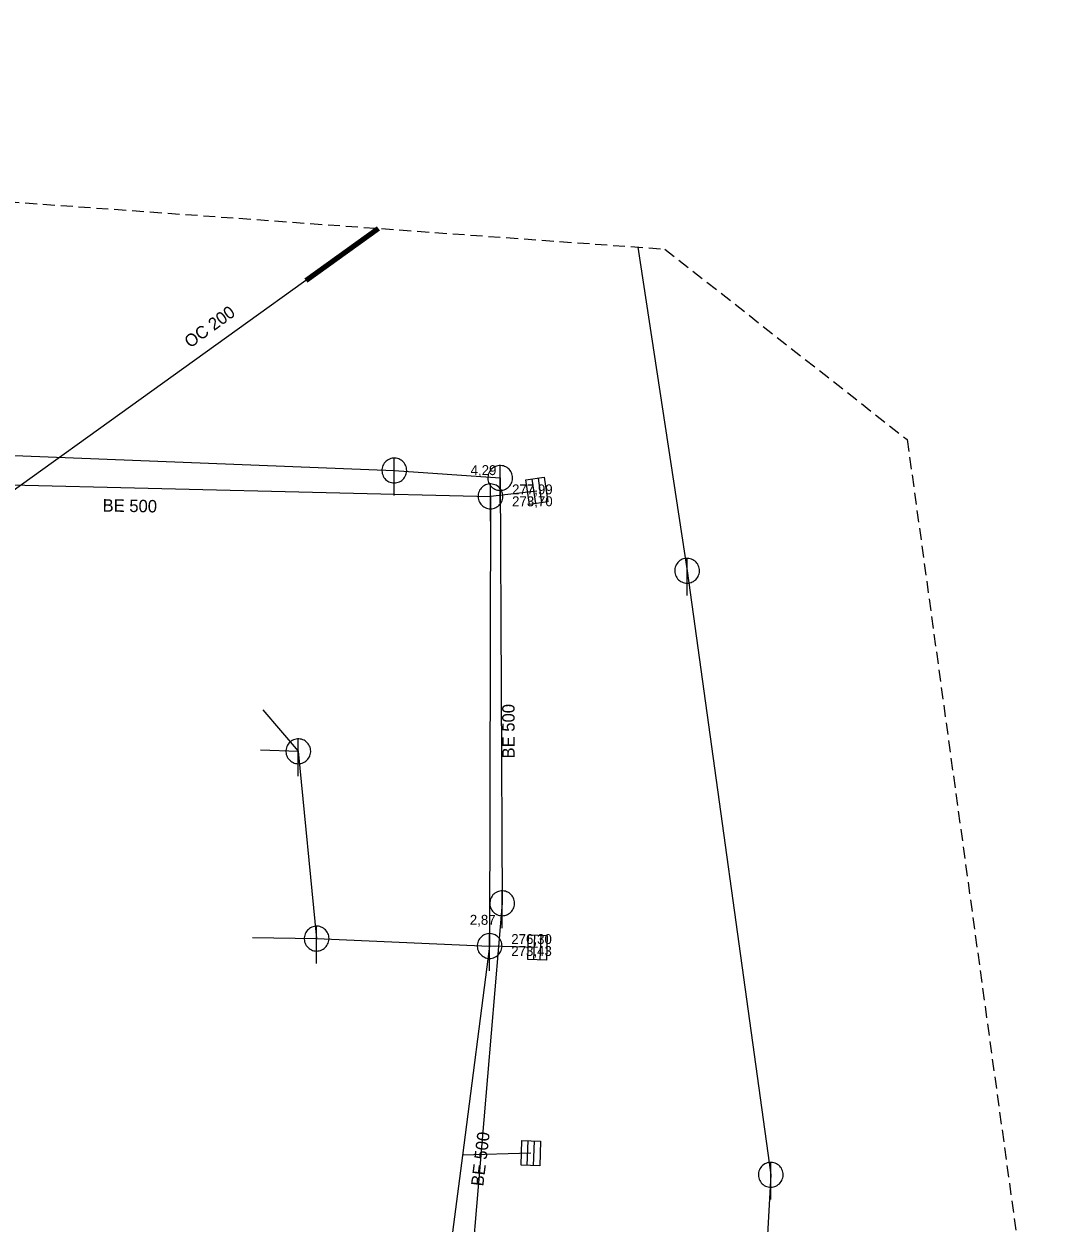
# Model space of a CAD drawing. Extents: x -725153 to -724843, y -978146 to -977794.
# Drawn here: x -724926.5 to -724842.7, y -977891.1 to -977794.5 of the extents above; entities that cross this region are included whole.
import ezdxf

# ---------------------------------------------------------------- set-up
doc = ezdxf.new("R2010")
doc.units = 0
doc.header["$LTSCALE"] = 0.32
doc.linetypes.add('MEDIUM_DASHED', pattern=[4.5, 3, -1.5])
doc.layers.add('1', color=7, linetype='Continuous')
for name, color, linetype, lineweight in [('11', 7, 'Continuous', 13), ('14', 7, 'Continuous', 25), ('17', 7, 'Continuous', 25), ('22', 7, 'Continuous', 13), ('3', 7, 'Continuous', 106), ('63', 7, 'MEDIUM_DASHED', 25)]:
    doc.layers.add(name, color=color, linetype=linetype, lineweight=lineweight)

msp = doc.modelspace()

# ---------------------------------------------------------------- linework, layer by layer
at = {"layer": '11'}
for p, q in [((-724885.159, -977832.094), (-724888.89, -977832.52)), ((-724907.243, -977849.713), (-724904.379, -977853.066)), ((-724907.421, -977852.944), (-724904.379, -977853.066)), ((-724904.379, -977853.066), (-724902.902, -977868.162)), ((-724908.07, -977868.07), (-724902.902, -977868.162)), ((-724902.902, -977868.162), (-724888.955, -977868.761)), ((-724885.092, -977868.873), (-724888.954, -977868.761)), ((-724885.628, -977885.445), (-724891.145, -977885.629))]:
    msp.add_line(p, q, dxfattribs=at)
at = {"layer": '14'}
for p, q in [((-724877.005, -977812.437), (-724873.038, -977838.517)), ((-724941.885, -977828.658), (-724896.642, -977830.439)), ((-724896.642, -977830.439), (-724888.104, -977831.037)), ((-724945.344, -977831.146), (-724888.89, -977832.52)), ((-724888.104, -977831.037), (-724887.943, -977865.316)), ((-724888.89, -977832.52), (-724888.955, -977868.761)), ((-724887.943, -977865.316), (-724890.881, -977899.822))]:
    msp.add_line(p, q, dxfattribs=at)
for points in [[(-724873.038, -977838.517), (-724866.293, -977887.198), (-724869.492, -977944.507)], [(-724888.955, -977868.761), (-724891.145, -977885.63), (-724893.153, -977901.096)]]:
    msp.add_lwpolyline(points, dxfattribs=at)
at = {"layer": '17'}
msp.add_lwpolyline([(-724897.93, -977810.925), (-724931.009, -977834.677), (-724933.379, -977835.594), (-724935.115, -977835.623)], dxfattribs=at)
at = {"layer": '22'}
for p, q in [((-724896.642, -977832.439), (-724896.641, -977829.439)), ((-724888.104, -977833.037), (-724888.103, -977830.037)), ((-724888.89, -977834.52), (-724888.889, -977831.52)), ((-724885.545, -977831.128), (-724885.257, -977833.107)), ((-724885.05, -977831.056), (-724884.762, -977833.035)), ((-724873.038, -977840.517), (-724873.037, -977837.517)), ((-724904.379, -977855.066), (-724904.378, -977852.066)), ((-724887.943, -977867.316), (-724887.942, -977864.316)), ((-724902.902, -977870.162), (-724902.901, -977867.162)), ((-724888.955, -977870.761), (-724888.954, -977867.761)), ((-724885.383, -977869.874), (-724885.313, -977867.875)), ((-724884.883, -977869.891), (-724884.814, -977867.893)), ((-724885.919, -977886.446), (-724885.849, -977884.447)), ((-724885.419, -977886.463), (-724885.35, -977884.465)), ((-724866.293, -977889.198), (-724866.292, -977886.198))]:
    msp.add_line(p, q, dxfattribs=at)
for points in [[(-724895.642, -977830.439), (-724895.647, -977830.33), (-724895.665, -977830.222), (-724895.695, -977830.116), (-724895.735, -977830.015), (-724895.787, -977829.918), (-724895.849, -977829.828), (-724895.921, -977829.745), (-724896.001, -977829.671), (-724896.089, -977829.605), (-724896.183, -977829.55), (-724896.283, -977829.505), (-724896.388, -977829.472), (-724896.495, -977829.45), (-724896.604, -977829.44), (-724896.714, -977829.442), (-724896.822, -977829.456), (-724896.929, -977829.481), (-724897.032, -977829.518), (-724897.13, -977829.567), (-724897.222, -977829.625), (-724897.308, -977829.694), (-724897.385, -977829.771), (-724897.454, -977829.857), (-724897.513, -977829.949), (-724897.561, -977830.047), (-724897.598, -977830.15), (-724897.624, -977830.257), (-724897.638, -977830.365), (-724897.641, -977830.475), (-724897.631, -977830.584), (-724897.61, -977830.691), (-724897.576, -977830.795), (-724897.532, -977830.895), (-724897.477, -977830.99), (-724897.411, -977831.078), (-724897.337, -977831.158), (-724897.254, -977831.23), (-724897.164, -977831.292), (-724897.068, -977831.344), (-724896.966, -977831.385), (-724896.861, -977831.415), (-724896.753, -977831.433), (-724896.643, -977831.439), (-724896.534, -977831.433), (-724896.426, -977831.415), (-724896.321, -977831.386), (-724896.219, -977831.345), (-724896.122, -977831.293), (-724896.032, -977831.231), (-724895.949, -977831.16), (-724895.874, -977831.08), (-724895.809, -977830.992), (-724895.753, -977830.898), (-724895.709, -977830.798), (-724895.675, -977830.694), (-724895.653, -977830.586), (-724895.643, -977830.477)], [(-724887.104, -977831.037), (-724887.109, -977830.928), (-724887.127, -977830.82), (-724887.157, -977830.714), (-724887.197, -977830.613), (-724887.249, -977830.516), (-724887.311, -977830.426), (-724887.383, -977830.343), (-724887.463, -977830.269), (-724887.551, -977830.203), (-724887.645, -977830.148), (-724887.745, -977830.103), (-724887.85, -977830.07), (-724887.957, -977830.048), (-724888.066, -977830.038), (-724888.176, -977830.04), (-724888.284, -977830.054), (-724888.391, -977830.079), (-724888.494, -977830.116), (-724888.592, -977830.165), (-724888.684, -977830.223), (-724888.77, -977830.292), (-724888.847, -977830.369), (-724888.916, -977830.455), (-724888.975, -977830.547), (-724889.023, -977830.645), (-724889.06, -977830.748), (-724889.086, -977830.855), (-724889.1, -977830.963), (-724889.103, -977831.073), (-724889.093, -977831.182), (-724889.072, -977831.289), (-724889.038, -977831.393), (-724888.994, -977831.493), (-724888.939, -977831.588), (-724888.873, -977831.676), (-724888.799, -977831.756), (-724888.716, -977831.828), (-724888.626, -977831.89), (-724888.53, -977831.942), (-724888.428, -977831.983), (-724888.323, -977832.013), (-724888.215, -977832.031), (-724888.105, -977832.037), (-724887.996, -977832.031), (-724887.888, -977832.013), (-724887.783, -977831.984), (-724887.681, -977831.943), (-724887.584, -977831.891), (-724887.494, -977831.829), (-724887.411, -977831.758), (-724887.336, -977831.678), (-724887.271, -977831.59), (-724887.215, -977831.496), (-724887.171, -977831.396), (-724887.137, -977831.292), (-724887.115, -977831.184), (-724887.105, -977831.075)], [(-724887.89, -977832.52), (-724887.895, -977832.411), (-724887.913, -977832.303), (-724887.943, -977832.197), (-724887.983, -977832.096), (-724888.035, -977831.999), (-724888.097, -977831.909), (-724888.169, -977831.826), (-724888.249, -977831.752), (-724888.337, -977831.686), (-724888.431, -977831.631), (-724888.531, -977831.586), (-724888.636, -977831.553), (-724888.743, -977831.531), (-724888.852, -977831.521), (-724888.962, -977831.523), (-724889.07, -977831.537), (-724889.177, -977831.562), (-724889.28, -977831.599), (-724889.378, -977831.648), (-724889.47, -977831.706), (-724889.556, -977831.775), (-724889.633, -977831.852), (-724889.702, -977831.938), (-724889.761, -977832.03), (-724889.809, -977832.128), (-724889.846, -977832.231), (-724889.872, -977832.338), (-724889.886, -977832.446), (-724889.889, -977832.556), (-724889.879, -977832.665), (-724889.858, -977832.772), (-724889.824, -977832.876), (-724889.78, -977832.976), (-724889.725, -977833.071), (-724889.659, -977833.159), (-724889.585, -977833.239), (-724889.502, -977833.311), (-724889.412, -977833.373), (-724889.316, -977833.425), (-724889.214, -977833.466), (-724889.109, -977833.496), (-724889.001, -977833.514), (-724888.891, -977833.52), (-724888.782, -977833.514), (-724888.674, -977833.496), (-724888.569, -977833.467), (-724888.467, -977833.426), (-724888.37, -977833.374), (-724888.28, -977833.312), (-724888.197, -977833.241), (-724888.122, -977833.161), (-724888.057, -977833.073), (-724888.001, -977832.979), (-724887.957, -977832.879), (-724887.923, -977832.775), (-724887.901, -977832.667), (-724887.891, -977832.558)], [(-724884.555, -977830.984), (-724884.268, -977832.963), (-724885.752, -977833.179), (-724886.04, -977831.2)], [(-724872.038, -977838.517), (-724872.043, -977838.408), (-724872.061, -977838.3), (-724872.091, -977838.194), (-724872.131, -977838.093), (-724872.183, -977837.996), (-724872.245, -977837.906), (-724872.317, -977837.823), (-724872.397, -977837.749), (-724872.485, -977837.683), (-724872.579, -977837.628), (-724872.679, -977837.583), (-724872.784, -977837.55), (-724872.891, -977837.528), (-724873, -977837.518), (-724873.11, -977837.52), (-724873.218, -977837.534), (-724873.325, -977837.559), (-724873.428, -977837.596), (-724873.526, -977837.645), (-724873.618, -977837.703), (-724873.704, -977837.772), (-724873.781, -977837.849), (-724873.85, -977837.935), (-724873.909, -977838.027), (-724873.957, -977838.125), (-724873.994, -977838.228), (-724874.02, -977838.335), (-724874.034, -977838.443), (-724874.037, -977838.553), (-724874.027, -977838.662), (-724874.006, -977838.769), (-724873.972, -977838.873), (-724873.928, -977838.973), (-724873.873, -977839.068), (-724873.807, -977839.156), (-724873.733, -977839.236), (-724873.65, -977839.308), (-724873.56, -977839.37), (-724873.464, -977839.422), (-724873.362, -977839.463), (-724873.257, -977839.493), (-724873.149, -977839.511), (-724873.039, -977839.517), (-724872.93, -977839.511), (-724872.822, -977839.493), (-724872.717, -977839.464), (-724872.615, -977839.423), (-724872.518, -977839.371), (-724872.428, -977839.309), (-724872.345, -977839.238), (-724872.27, -977839.158), (-724872.205, -977839.07), (-724872.149, -977838.976), (-724872.105, -977838.876), (-724872.071, -977838.772), (-724872.049, -977838.664), (-724872.039, -977838.555)], [(-724903.379, -977853.066), (-724903.384, -977852.957), (-724903.402, -977852.849), (-724903.432, -977852.743), (-724903.472, -977852.642), (-724903.524, -977852.545), (-724903.586, -977852.455), (-724903.658, -977852.372), (-724903.738, -977852.298), (-724903.826, -977852.232), (-724903.92, -977852.177), (-724904.02, -977852.132), (-724904.125, -977852.099), (-724904.232, -977852.077), (-724904.341, -977852.067), (-724904.451, -977852.069), (-724904.559, -977852.083), (-724904.666, -977852.108), (-724904.769, -977852.145), (-724904.867, -977852.194), (-724904.959, -977852.252), (-724905.045, -977852.321), (-724905.122, -977852.398), (-724905.191, -977852.484), (-724905.25, -977852.576), (-724905.298, -977852.674), (-724905.335, -977852.777), (-724905.361, -977852.884), (-724905.375, -977852.992), (-724905.378, -977853.102), (-724905.368, -977853.211), (-724905.347, -977853.318), (-724905.313, -977853.422), (-724905.269, -977853.522), (-724905.214, -977853.617), (-724905.148, -977853.705), (-724905.074, -977853.785), (-724904.991, -977853.857), (-724904.901, -977853.919), (-724904.805, -977853.971), (-724904.703, -977854.012), (-724904.598, -977854.042), (-724904.49, -977854.06), (-724904.38, -977854.066), (-724904.271, -977854.06), (-724904.163, -977854.042), (-724904.058, -977854.013), (-724903.956, -977853.972), (-724903.859, -977853.92), (-724903.769, -977853.858), (-724903.686, -977853.787), (-724903.611, -977853.707), (-724903.546, -977853.619), (-724903.49, -977853.525), (-724903.446, -977853.425), (-724903.412, -977853.321), (-724903.39, -977853.213), (-724903.38, -977853.104)], [(-724886.943, -977865.316), (-724886.948, -977865.207), (-724886.966, -977865.099), (-724886.996, -977864.993), (-724887.036, -977864.892), (-724887.088, -977864.795), (-724887.15, -977864.705), (-724887.222, -977864.622), (-724887.302, -977864.548), (-724887.39, -977864.482), (-724887.484, -977864.427), (-724887.584, -977864.382), (-724887.689, -977864.349), (-724887.796, -977864.327), (-724887.905, -977864.317), (-724888.015, -977864.319), (-724888.123, -977864.333), (-724888.23, -977864.358), (-724888.333, -977864.395), (-724888.431, -977864.444), (-724888.523, -977864.502), (-724888.609, -977864.571), (-724888.686, -977864.648), (-724888.755, -977864.734), (-724888.814, -977864.826), (-724888.862, -977864.924), (-724888.899, -977865.027), (-724888.925, -977865.134), (-724888.939, -977865.242), (-724888.942, -977865.352), (-724888.932, -977865.461), (-724888.911, -977865.568), (-724888.877, -977865.672), (-724888.833, -977865.772), (-724888.778, -977865.867), (-724888.712, -977865.955), (-724888.638, -977866.035), (-724888.555, -977866.107), (-724888.465, -977866.169), (-724888.369, -977866.221), (-724888.267, -977866.262), (-724888.162, -977866.292), (-724888.054, -977866.31), (-724887.944, -977866.316), (-724887.835, -977866.31), (-724887.727, -977866.292), (-724887.622, -977866.263), (-724887.52, -977866.222), (-724887.423, -977866.17), (-724887.333, -977866.108), (-724887.25, -977866.037), (-724887.175, -977865.957), (-724887.11, -977865.869), (-724887.054, -977865.775), (-724887.01, -977865.675), (-724886.976, -977865.571), (-724886.954, -977865.463), (-724886.944, -977865.354)], [(-724901.902, -977868.162), (-724901.907, -977868.053), (-724901.925, -977867.945), (-724901.955, -977867.839), (-724901.995, -977867.738), (-724902.047, -977867.641), (-724902.109, -977867.551), (-724902.181, -977867.468), (-724902.261, -977867.394), (-724902.349, -977867.328), (-724902.443, -977867.273), (-724902.543, -977867.228), (-724902.648, -977867.195), (-724902.755, -977867.173), (-724902.864, -977867.163), (-724902.974, -977867.165), (-724903.082, -977867.179), (-724903.189, -977867.204), (-724903.292, -977867.241), (-724903.39, -977867.29), (-724903.482, -977867.348), (-724903.568, -977867.417), (-724903.645, -977867.494), (-724903.714, -977867.58), (-724903.773, -977867.672), (-724903.821, -977867.77), (-724903.858, -977867.873), (-724903.884, -977867.98), (-724903.898, -977868.088), (-724903.901, -977868.198), (-724903.891, -977868.307), (-724903.87, -977868.414), (-724903.836, -977868.518), (-724903.792, -977868.618), (-724903.737, -977868.713), (-724903.671, -977868.801), (-724903.597, -977868.881), (-724903.514, -977868.953), (-724903.424, -977869.015), (-724903.328, -977869.067), (-724903.226, -977869.108), (-724903.121, -977869.138), (-724903.013, -977869.156), (-724902.903, -977869.162), (-724902.794, -977869.156), (-724902.686, -977869.138), (-724902.581, -977869.109), (-724902.479, -977869.068), (-724902.382, -977869.016), (-724902.292, -977868.954), (-724902.209, -977868.883), (-724902.134, -977868.803), (-724902.069, -977868.715), (-724902.013, -977868.621), (-724901.969, -977868.521), (-724901.935, -977868.417), (-724901.913, -977868.309), (-724901.903, -977868.2)], [(-724887.955, -977868.761), (-724887.96, -977868.652), (-724887.978, -977868.544), (-724888.008, -977868.438), (-724888.048, -977868.337), (-724888.1, -977868.24), (-724888.162, -977868.15), (-724888.234, -977868.067), (-724888.314, -977867.993), (-724888.402, -977867.927), (-724888.496, -977867.872), (-724888.596, -977867.827), (-724888.701, -977867.794), (-724888.808, -977867.772), (-724888.917, -977867.762), (-724889.027, -977867.764), (-724889.135, -977867.778), (-724889.242, -977867.803), (-724889.345, -977867.84), (-724889.443, -977867.889), (-724889.535, -977867.947), (-724889.621, -977868.016), (-724889.698, -977868.093), (-724889.767, -977868.179), (-724889.826, -977868.271), (-724889.874, -977868.369), (-724889.911, -977868.472), (-724889.937, -977868.579), (-724889.951, -977868.687), (-724889.954, -977868.797), (-724889.944, -977868.906), (-724889.923, -977869.013), (-724889.889, -977869.117), (-724889.845, -977869.217), (-724889.79, -977869.312), (-724889.724, -977869.4), (-724889.65, -977869.48), (-724889.567, -977869.552), (-724889.477, -977869.614), (-724889.381, -977869.666), (-724889.279, -977869.707), (-724889.174, -977869.737), (-724889.066, -977869.755), (-724888.956, -977869.761), (-724888.847, -977869.755), (-724888.739, -977869.737), (-724888.634, -977869.708), (-724888.532, -977869.667), (-724888.435, -977869.615), (-724888.345, -977869.553), (-724888.262, -977869.482), (-724888.187, -977869.402), (-724888.122, -977869.314), (-724888.066, -977869.22), (-724888.022, -977869.12), (-724887.988, -977869.016), (-724887.966, -977868.908), (-724887.956, -977868.799)], [(-724885.883, -977869.857), (-724885.813, -977867.858), (-724884.314, -977867.91), (-724884.384, -977869.909)], [(-724886.419, -977886.429), (-724886.349, -977884.43), (-724884.85, -977884.482), (-724884.92, -977886.481)], [(-724865.293, -977887.198), (-724865.298, -977887.089), (-724865.316, -977886.981), (-724865.346, -977886.875), (-724865.386, -977886.774), (-724865.438, -977886.677), (-724865.5, -977886.587), (-724865.572, -977886.504), (-724865.652, -977886.43), (-724865.74, -977886.364), (-724865.834, -977886.309), (-724865.934, -977886.264), (-724866.039, -977886.231), (-724866.146, -977886.209), (-724866.255, -977886.199), (-724866.365, -977886.201), (-724866.473, -977886.215), (-724866.58, -977886.24), (-724866.683, -977886.277), (-724866.781, -977886.326), (-724866.873, -977886.384), (-724866.959, -977886.453), (-724867.036, -977886.53), (-724867.105, -977886.616), (-724867.164, -977886.708), (-724867.212, -977886.806), (-724867.249, -977886.909), (-724867.275, -977887.016), (-724867.289, -977887.124), (-724867.292, -977887.234), (-724867.282, -977887.343), (-724867.261, -977887.45), (-724867.227, -977887.554), (-724867.183, -977887.654), (-724867.128, -977887.749), (-724867.062, -977887.837), (-724866.988, -977887.917), (-724866.905, -977887.989), (-724866.815, -977888.051), (-724866.719, -977888.103), (-724866.617, -977888.144), (-724866.512, -977888.174), (-724866.404, -977888.192), (-724866.294, -977888.198), (-724866.185, -977888.192), (-724866.077, -977888.174), (-724865.972, -977888.145), (-724865.87, -977888.104), (-724865.773, -977888.052), (-724865.683, -977887.99), (-724865.6, -977887.919), (-724865.525, -977887.839), (-724865.46, -977887.751), (-724865.404, -977887.657), (-724865.36, -977887.557), (-724865.326, -977887.453), (-724865.304, -977887.345), (-724865.294, -977887.236)]]:
    msp.add_lwpolyline(points, close=True, dxfattribs=at)
at = {"layer": '3'}
msp.add_line((-724897.93, -977810.925), (-724903.764, -977815.114), dxfattribs=at)
at = {"layer": '3', "lineweight": 100}
msp.add_line((-724897.93, -977810.925), (-724903.764, -977815.114), dxfattribs=at)
at = {"layer": '63'}
msp.add_lwpolyline([(-725126.038, -977904.704), (-725126.038, -977794.451), (-724874.829, -977812.594), (-724855.29, -977827.945), (-724842.73, -977919.358), (-724859.477, -977998.21), (-724911.114, -978092.413), (-724961.356, -978146.144), (-725152.554, -978126.605)], close=True, dxfattribs=at)

# ---------------------------------------------------------------- texts
at = {"layer": '1'}
for s, rotation, p in [('OC 200', 36, (-724913.104, -977820.607)), ('BE 500', 359, (-724920.164, -977833.743)), ('BE 500', 90, (-724886.942, -977853.643)), ('BE 500', 83, (-724889.471, -977888.158))]:
    msp.add_text(s, height=1, rotation=rotation, dxfattribs=at).set_placement(p)
for s, p in [('4,29', (-724890.49, -977830.808)), ('2,87', (-724890.555, -977867.049))]:
    msp.add_text(s, height=0.8, dxfattribs=at).set_placement(p)
at = {"layer": '22'}
for s, p in [('277,99', (-724887.147, -977832.36)), ('273,70', (-724887.147, -977833.32)), ('276,30', (-724887.212, -977868.6)), ('273,43', (-724887.212, -977869.56))]:
    msp.add_text(s, height=0.8, dxfattribs=at).set_placement(p)

doc.saveas('drawing.dxf')
